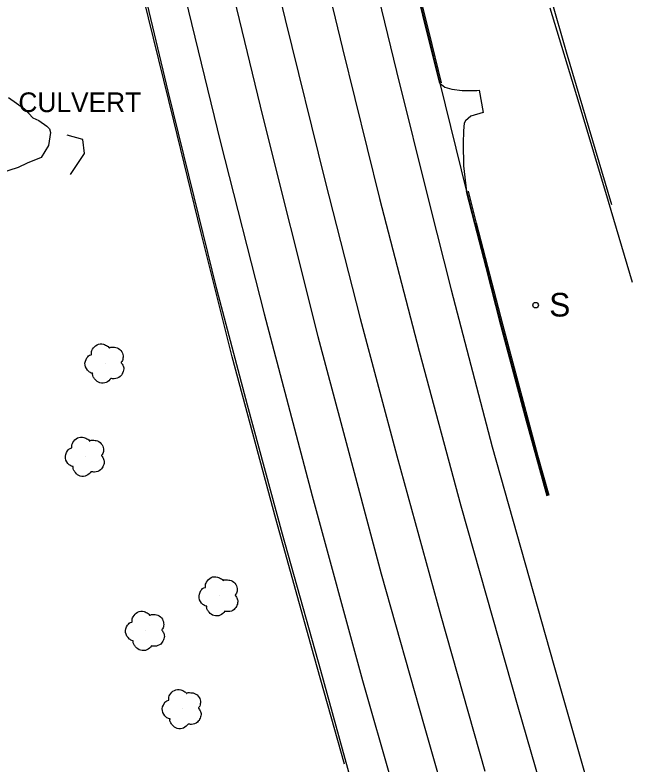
# Model space of a CAD drawing. Extents: x 368532 to 392481, y 10654822 to 10676899.
# Drawn here: x 375924.4 to 376081.2, y 10666341.6 to 10666532 of the extents above; entities that cross this region are included whole.
import ezdxf

# ---------------------------------------------------------------- set-up
doc = ezdxf.new("R2010")
doc.units = 0
for name, color, linetype in [('p_drainage conc drain', 7, 'Continuous'), ('p_drainage culvert', 7, 'Continuous'), ('p_road - paved curb', 7, 'Continuous'), ('p_road guard rails', 7, 'Continuous'), ('p_road paint stripe', 7, 'Continuous'), ('p_structure sign', 7, 'Continuous'), ('p_veg tree', 7, 'Continuous'), ('p_veg woods', 7, 'Continuous')]:
    doc.layers.add(name, color=color, linetype=linetype)

msp = doc.modelspace()

# ---------------------------------------------------------------- linework, layer by layer
at = {"layer": 'p_drainage conc drain'}
for p, q in [((376032.33, 10666514.64), (376033.58, 10666513.66)), ((376033.58, 10666513.66), (376035.36, 10666513.1)), ((376035.36, 10666513.1), (376038.04, 10666512.82)), ((376038.04, 10666512.82), (376041.71, 10666512.78)), ((376041.71, 10666512.78), (376042.33, 10666512.85)), ((376042.33, 10666512.85), (376043.4, 10666507.21)), ((376043.4, 10666507.21), (376040.2, 10666506.28)), ((376038.9, 10666505.09), (376038.57, 10666504.48)), ((376040.2, 10666506.28), (376038.9, 10666505.09)), ((376038.57, 10666504.48), (376038.35, 10666502.58)), ((376038.35, 10666502.58), (376038.28, 10666499.33)), ((376038.28, 10666499.33), (376038.38, 10666493.61)), ((376038.38, 10666493.61), (376039.12, 10666487.11))]:
    msp.add_line(p, q, dxfattribs=at)
at = {"layer": 'p_drainage culvert'}
for p, q in [((375941.64, 10666500.36), (375937.64, 10666501.42)), ((375942.07, 10666496.76), (375941.64, 10666500.36)), ((375938.51, 10666491.46), (375942.07, 10666496.76))]:
    msp.add_line(p, q, dxfattribs=at)
at = {"layer": 'p_road - paved curb'}
for p, q in [((376064.53, 10666522.58), (376055.09, 10666555.24)), ((376029.17, 10666527.49), (376025.19, 10666543.63)), ((376029.32, 10666527.53), (376025.34, 10666543.67)), ((376029.66, 10666527.61), (376025.68, 10666543.75)), ((375963.35, 10666512.64), (375956.8, 10666540.12)), ((376032.33, 10666514.64), (376029.17, 10666527.49)), ((376032.47, 10666514.67), (376029.32, 10666527.53)), ((376032.81, 10666514.75), (376029.66, 10666527.61)), ((376076.09, 10666483.78), (376064.53, 10666522.58)), ((376032.33, 10666514.64), (376039.12, 10666487.11)), ((375969.94, 10666485.75), (375963.35, 10666512.64)), ((375975.72, 10666462.33), (375969.94, 10666485.75)), ((376041.22, 10666478.93), (376039.12, 10666487.11)), ((376041.37, 10666478.97), (376039.26, 10666487.15)), ((376041.7, 10666479.05), (376039.6, 10666487.24)), ((376044.09, 10666467.82), (376041.22, 10666478.93)), ((376044.24, 10666467.86), (376041.37, 10666478.97)), ((376044.57, 10666467.94), (376041.7, 10666479.05)), ((376047.85, 10666453.15), (376044.09, 10666467.82)), ((376048, 10666453.19), (376044.24, 10666467.86)), ((376048.33, 10666453.28), (376044.57, 10666467.94)), ((375983.45, 10666432.85), (375975.72, 10666462.33)), ((376052.31, 10666438.41), (376048.33, 10666453.28)), ((376051.83, 10666438.28), (376047.85, 10666453.15)), ((376051.97, 10666438.32), (376048, 10666453.19)), ((376054.37, 10666428.76), (376051.83, 10666438.28)), ((376054.51, 10666428.8), (376051.97, 10666438.32)), ((376054.85, 10666428.89), (376052.31, 10666438.41)), ((375992.35, 10666400), (375983.45, 10666432.85)), ((376056.81, 10666419.88), (376054.37, 10666428.76)), ((376056.95, 10666419.92), (376054.51, 10666428.8)), ((376057.29, 10666420.01), (376054.85, 10666428.89)), ((376059.61, 10666409.71), (376056.81, 10666419.88)), ((376059.75, 10666409.75), (376056.95, 10666419.92)), ((376060.09, 10666409.84), (376057.29, 10666420.01)), ((376002.1, 10666365.39), (375992.35, 10666400)), ((376011.32, 10666331.89), (376002.1, 10666365.39))]:
    msp.add_line(p, q, dxfattribs=at)
at = {"layer": 'p_road guard rails'}
for p, q in [((375964.72, 10666505.11), (375956.37, 10666539.18)), ((376060.32, 10666533.85), (376067.66, 10666509.55)), ((376067.66, 10666509.55), (376075.13, 10666484.68)), ((375971.7, 10666476.63), (375964.72, 10666505.11)), ((376075.13, 10666484.68), (376081.18, 10666464.07)), ((375979.61, 10666445.08), (375971.7, 10666476.63)), ((375990.71, 10666403.89), (375979.61, 10666445.08)), ((376000.46, 10666368.95), (375990.71, 10666403.89)), ((376008.15, 10666341.54), (376000.46, 10666368.95))]:
    msp.add_line(p, q, dxfattribs=at)
at = {"layer": 'p_road paint stripe'}
for p, q in [((375996.39, 10666570.48), (376007.63, 10666523.47)), ((375984.2, 10666568.06), (375993.06, 10666530.82)), ((376012.72, 10666553.09), (376021.33, 10666517.59)), ((375965.43, 10666545.43), (375976.61, 10666499.55)), ((375977.93, 10666544.93), (375987.36, 10666505.99)), ((375993.06, 10666530.82), (376003.17, 10666490.02)), ((376007.63, 10666523.47), (376017.03, 10666485.38)), ((376021.33, 10666517.59), (376029.76, 10666483.92)), ((375987.36, 10666505.99), (376001.31, 10666450.29)), ((375976.61, 10666499.55), (375987.73, 10666456)), ((376003.17, 10666490.02), (376012.14, 10666454.81)), ((376017.03, 10666485.38), (376027.07, 10666446.52)), ((376029.76, 10666483.92), (376035.27, 10666462.13)), ((376035.27, 10666462.13), (376045.68, 10666422.26)), ((375987.73, 10666456), (375999.88, 10666409.74)), ((376012.14, 10666454.81), (376021.42, 10666419.95)), ((376001.31, 10666450.29), (376007.5, 10666427.14)), ((376027.07, 10666446.52), (376037.65, 10666407.21)), ((376007.5, 10666427.14), (376017.47, 10666389.94)), ((376045.68, 10666422.26), (376061.33, 10666366.72)), ((376021.42, 10666419.95), (376032.6, 10666379.28)), ((375999.88, 10666409.74), (376012.71, 10666362.87)), ((376037.65, 10666407.21), (376052.14, 10666356.18)), ((376017.47, 10666389.94), (376028.35, 10666351.33)), ((376032.6, 10666379.28), (376043.76, 10666339.8)), ((376061.33, 10666366.72), (376074.07, 10666322.34)), ((376012.71, 10666362.87), (376022.49, 10666328.72)), ((376052.14, 10666356.18), (376067.98, 10666301.32)), ((376028.35, 10666351.33), (376040, 10666311.15))]:
    msp.add_line(p, q, dxfattribs=at)
at = {"layer": 'p_structure sign'}
msp.add_circle((376056.69, 10666458.24), 0.713, dxfattribs=at)
at = {"layer": 'p_veg tree'}
for p, q in [((375947.32, 10666443.51), (375947.32, 10666443.51)), ((375942.34, 10666419.83), (375942.34, 10666419.83)), ((375976.3, 10666384.33), (375976.3, 10666384.33)), ((375957.64, 10666375.53), (375957.64, 10666375.53)), ((375966.97, 10666355.67), (375966.97, 10666355.67))]:
    msp.add_line(p, q, dxfattribs=at)
for points in [[(375948.76, 10666439.61), (375947.58, 10666438.59), (375945.97, 10666438.49), (375944.74, 10666439.35), (375944.27, 10666440.06), (375944.13, 10666440.75), (375944.13, 10666440.9), (375944.03, 10666440.93), (375943.17, 10666441.35), (375942.19, 10666443.01), (375942.68, 10666444.86), (375943.72, 10666445.65), (375943.86, 10666445.7), (375943.85, 10666445.82), (375944.1, 10666447.01), (375945.24, 10666448.16), (375946.91, 10666448.32), (375947.88, 10666447.83), (375948.28, 10666447.46), (375948.34, 10666447.36), (375948.42, 10666447.43), (375949.07, 10666447.6), (375950.34, 10666447.41), (375951.53, 10666446.38), (375951.86, 10666445.03), (375951.54, 10666443.94), (375951.39, 10666443.72), (375951.38, 10666443.65), (375951.42, 10666443.6), (375951.67, 10666443.22), (375952.02, 10666442.31), (375951.81, 10666441.12), (375951.1, 10666440.07), (375949.6, 10666439.51), (375948.74, 10666439.6)], [(375943.79, 10666415.92), (375942.6, 10666414.91), (375940.99, 10666414.81), (375939.76, 10666415.66), (375939.29, 10666416.38), (375939.15, 10666417.06), (375939.15, 10666417.21), (375939.05, 10666417.25), (375938.19, 10666417.67), (375937.21, 10666419.33), (375937.7, 10666421.18), (375938.74, 10666421.96), (375938.88, 10666422.02), (375938.87, 10666422.14), (375939.12, 10666423.33), (375940.26, 10666424.48), (375941.93, 10666424.63), (375942.9, 10666424.15), (375943.3, 10666423.78), (375943.36, 10666423.68), (375943.44, 10666423.75), (375944.09, 10666423.91), (375945.36, 10666423.73), (375946.55, 10666422.7), (375946.88, 10666421.35), (375946.56, 10666420.26), (375946.41, 10666420.04), (375946.4, 10666419.97), (375946.44, 10666419.92), (375946.69, 10666419.54), (375947.04, 10666418.63), (375946.83, 10666417.43), (375946.12, 10666416.39), (375944.62, 10666415.82), (375943.76, 10666415.91)], [(375977.75, 10666380.43), (375976.56, 10666379.42), (375974.96, 10666379.32), (375973.72, 10666380.17), (375973.25, 10666380.88), (375973.11, 10666381.57), (375973.12, 10666381.72), (375973.01, 10666381.75), (375972.15, 10666382.18), (375971.17, 10666383.84), (375971.66, 10666385.69), (375972.7, 10666386.47), (375972.84, 10666386.53), (375972.83, 10666386.65), (375973.09, 10666387.84), (375974.22, 10666388.99), (375975.89, 10666389.14), (375976.86, 10666388.66), (375977.27, 10666388.28), (375977.33, 10666388.19), (375977.4, 10666388.26), (375978.06, 10666388.42), (375979.32, 10666388.24), (375980.51, 10666387.21), (375980.84, 10666385.86), (375980.53, 10666384.76), (375980.37, 10666384.55), (375980.37, 10666384.48), (375980.4, 10666384.43), (375980.65, 10666384.05), (375981, 10666383.14), (375980.79, 10666381.94), (375980.08, 10666380.9), (375978.58, 10666380.33), (375977.73, 10666380.42)], [(375959.09, 10666371.63), (375957.91, 10666370.62), (375956.3, 10666370.51), (375955.06, 10666371.37), (375954.59, 10666372.08), (375954.45, 10666372.77), (375954.46, 10666372.92), (375954.35, 10666372.95), (375953.49, 10666373.37), (375952.51, 10666375.04), (375953.01, 10666376.88), (375954.04, 10666377.67), (375954.18, 10666377.73), (375954.17, 10666377.85), (375954.43, 10666379.04), (375955.57, 10666380.18), (375957.23, 10666380.34), (375958.21, 10666379.86), (375958.61, 10666379.48), (375958.67, 10666379.39), (375958.75, 10666379.46), (375959.4, 10666379.62), (375960.67, 10666379.44), (375961.85, 10666378.41), (375962.18, 10666377.05), (375961.87, 10666375.96), (375961.71, 10666375.75), (375961.71, 10666375.68), (375961.74, 10666375.62), (375961.99, 10666375.24), (375962.34, 10666374.33), (375962.13, 10666373.14), (375961.42, 10666372.1), (375959.92, 10666371.53), (375959.07, 10666371.62)], [(375968.42, 10666351.77), (375967.23, 10666350.75), (375965.62, 10666350.65), (375964.39, 10666351.51), (375963.92, 10666352.22), (375963.78, 10666352.91), (375963.79, 10666353.06), (375963.68, 10666353.09), (375962.82, 10666353.51), (375961.84, 10666355.17), (375962.33, 10666357.02), (375963.37, 10666357.81), (375963.51, 10666357.86), (375963.5, 10666357.98), (375963.76, 10666359.17), (375964.89, 10666360.32), (375966.56, 10666360.48), (375967.53, 10666359.99), (375967.94, 10666359.62), (375968, 10666359.52), (375968.07, 10666359.59), (375968.72, 10666359.76), (375969.99, 10666359.57), (375971.18, 10666358.54), (375971.51, 10666357.19), (375971.19, 10666356.1), (375971.04, 10666355.88), (375971.03, 10666355.81), (375971.07, 10666355.76), (375971.32, 10666355.38), (375971.67, 10666354.47), (375971.46, 10666353.28), (375970.75, 10666352.23), (375969.25, 10666351.67), (375968.39, 10666351.76)]]:
    msp.add_spline(points, degree=3, dxfattribs=at)
at = {"layer": 'p_veg woods'}
msp.add_lwpolyline([(375922.71, 10666510.98), (375926.83, 10666508.18), (375928.9, 10666505.87), (375930.45, 10666505.19), (375932.5, 10666503.72), (375933.2, 10666503.09), (375933.44, 10666502.09), (375932.91, 10666498.84), (375931.02, 10666495.76), (375927.48, 10666494.3), (375925.17, 10666493.22), (375920.35, 10666491.69)], dxfattribs=at)

# ---------------------------------------------------------------- texts
at = {"layer": 'p_drainage culvert'}
msp.add_text(' CULVERT', height=5, dxfattribs=at).set_placement((375923.41, 10666507.31))
at = {"layer": 'p_structure sign'}
msp.add_text('S', height=6, dxfattribs=at).set_placement((376060.15, 10666455.35))

doc.saveas('drawing.dxf')
